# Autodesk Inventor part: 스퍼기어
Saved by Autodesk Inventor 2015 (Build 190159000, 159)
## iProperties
Created: 2024-12
Part Number: 스퍼기어
Material: 일반
Document SubType Name: Modeling
Designer: 102-5
Density: 1 g/cm^3
Appearance: 기본값
Author: 102-5
Author: jhkim
Creation Date: 2024-11-28
Sending System: Autodesk Inventor 2025
Preprocessor: ST-DEVELOPER v20
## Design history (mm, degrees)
node "스퍼기어1"
node "솔리드1"
node "기준1"
